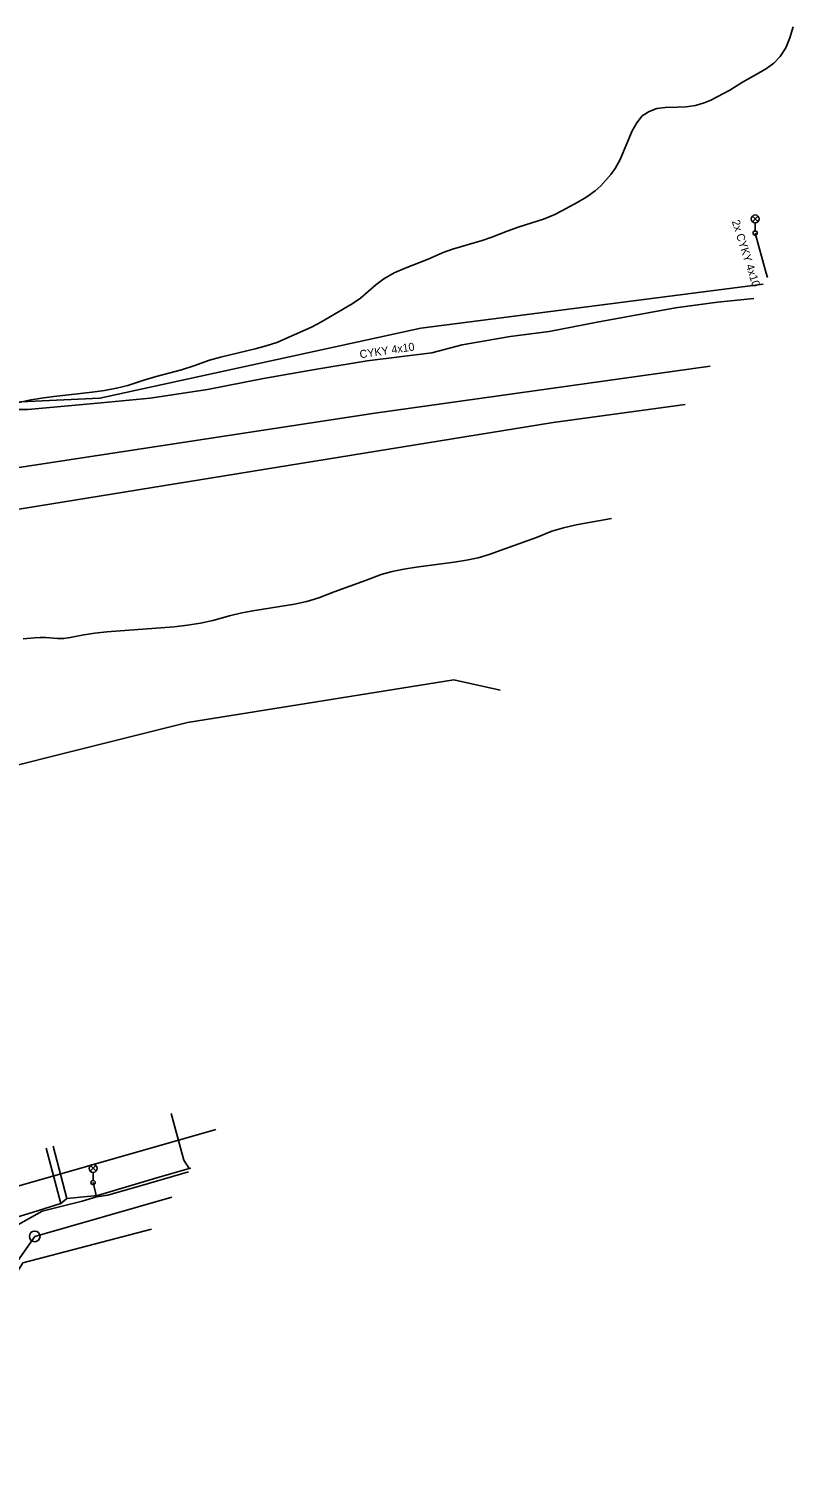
# Model space of a CAD drawing. Extents: x -737422 to -734235, y -1145631 to -1142623.
# Drawn here: x -736808.9 to -736737.2, y -1144825.6 to -1144691 of the extents above; entities that cross this region are included whole.
import ezdxf

# ---------------------------------------------------------------- set-up
doc = ezdxf.new("R2010")
doc.units = 0
for name, color, linetype in [('Vrstva 1', 7, 'Continuous'), ('Vrstva 20', 7, 'Continuous'), ('Vrstva 3', 7, 'Continuous'), ('Vrstva 30', 7, 'Continuous'), ('Vrstva 34', 7, 'Continuous'), ('Vrstva 40', 7, 'Continuous'), ('Vrstva 41', 7, 'Continuous'), ('Vrstva 44', 7, 'Continuous'), ('Vrstva 48', 7, 'Continuous')]:
    doc.layers.add(name, color=color, linetype=linetype)

# ---------------------------------------------------------------- blocks, each defined once
blk = doc.blocks.new('6.200')
at = {"layer": 'Vrstva 1'}
blk.add_circle((0, 0), 1, dxfattribs=at)
blk = doc.blocks.new('6.560')
at = {"layer": 'Vrstva 1'}
for p, q in [((-0.528, 2.124), (0.528, 3.18)), ((0.544, 2.13), (-0.512, 3.188)), ((0, 1.9), (0, 0.4))]:
    blk.add_line(p, q, dxfattribs=at)
for centre, radius in [((0, 2.65), 0.75), ((0, 0), 0.4)]:
    blk.add_circle(centre, radius, dxfattribs=at)

msp = doc.modelspace()

# ---------------------------------------------------------------- linework, layer by layer
at = {"layer": 'Vrstva 1'}
for points in [[(-736737.175, -1144690.787), (-736737.486, -1144691.814), (-736737.879, -1144692.76), (-736738.396, -1144693.582), (-736738.991, -1144694.188), (-736739.681, -1144694.696), (-736740.427, -1144695.142), (-736741.943, -1144695.981), (-736743.129, -1144696.713), (-736743.73, -1144697.046), (-736744.923, -1144697.656), (-736745.521, -1144697.915), (-736746.361, -1144698.156), (-736747.218, -1144698.289), (-736748.049, -1144698.335), (-736749.202, -1144698.341), (-736749.965, -1144698.454), (-736750.696, -1144698.713), (-736751.342, -1144699.146), (-736751.862, -1144699.774), (-736752.286, -1144700.55), (-736753.411, -1144703.224), (-736753.875, -1144704.066), (-736754.292, -1144704.637), (-736754.748, -1144705.172), (-736755.228, -1144705.688), (-736755.747, -1144706.167), (-736756.525, -1144706.723), (-736757.369, -1144707.215), (-736758.879, -1144708.047), (-736759.542, -1144708.387), (-736760.614, -1144708.821)], [(-736760.614, -1144708.821), (-736762.896, -1144709.548), (-736764.015, -1144709.933), (-736765.449, -1144710.504), (-736766.346, -1144710.81), (-736769.126, -1144711.636), (-736770.01, -1144711.953), (-736771.405, -1144712.56), (-736773.565, -1144713.402), (-736774.613, -1144713.854), (-736775.572, -1144714.395), (-736776.323, -1144714.978), (-736777.754, -1144716.215), (-736778.549, -1144716.753), (-736781.483, -1144718.486), (-736782.373, -1144718.93), (-736785.609, -1144720.361), (-736786.604, -1144720.699), (-736787.656, -1144720.98), (-736790.9, -1144721.737), (-736791.928, -1144722.042), (-736793.396, -1144722.574), (-736794.542, -1144722.928), (-736796.916, -1144723.554), (-736798.074, -1144723.896), (-736799.574, -1144724.395), (-736800.639, -1144724.664), (-736801.764, -1144724.872), (-736802.931, -1144725.039), (-736806.518, -1144725.452), (-736807.696, -1144725.607), (-736808.841, -1144725.796), (-736809.936, -1144726.034)], [(-736782.787, -1144744.637), (-736781.679, -1144744.312), (-736780.238, -1144743.747), (-736777.288, -1144742.687), (-736775.838, -1144742.133), (-736774.796, -1144741.839), (-736773.689, -1144741.611), (-736772.537, -1144741.427), (-736768.992, -1144740.961), (-736767.838, -1144740.778), (-736766.729, -1144740.549), (-736765.684, -1144740.255), (-736764.229, -1144739.701), (-736761.267, -1144738.638), (-736759.822, -1144738.069), (-736758.714, -1144737.738), (-736757.54, -1144737.474), (-736754.23, -1144736.872)], [(-736809.405, -1144748.166), (-736808.351, -1144748.044), (-736807.809, -1144748.017), (-736807.263, -1144748.032), (-736806.172, -1144748.118), (-736805.587, -1144748.109), (-736804.979, -1144748.041), (-736803.698, -1144747.782), (-736802.673, -1144747.617), (-736801.545, -1144747.49), (-736795.248, -1144747.012), (-736793.989, -1144746.872), (-736792.771, -1144746.686), (-736791.613, -1144746.438), (-736790.045, -1144745.994), (-736788.879, -1144745.723), (-736787.665, -1144745.5), (-736783.965, -1144744.893), (-736782.787, -1144744.637)], [(-736793.84, -1144797.81), (-736794.33, -1144797.02), (-736795.51, -1144792.65)], [(-736805.86, -1144801.09), (-736807.23, -1144795.89)], [(-736806.59, -1144795.7), (-736805.31, -1144800.62)], [(-736793.84, -1144797.81), (-736796.85, -1144798.66), (-736802.43, -1144800.32)], [(-736793.84, -1144797.81), (-736793.68, -1144797.762)], [(-736802.43, -1144800.32), (-736805.31, -1144800.62)], [(-736814.21, -1144804.51), (-736813.42, -1144803.39), (-736808.97, -1144802.03), (-736805.86, -1144801.09)], [(-736805.31, -1144800.62), (-736805.86, -1144801.09)]]:
    msp.add_lwpolyline(points, dxfattribs=at)
at = {"layer": 'Vrstva 20'}
for points in [[(-736817.09, -1144726.28), (-736802.2, -1144725.6), (-736772.1, -1144719.03), (-736740.001, -1144714.909)], [(-736816.76, -1144825.61), (-736826.1, -1144822.58), (-736824.46, -1144814.68), (-736820.13, -1144804.66), (-736815.63, -1144801.09), (-736791.34, -1144794.15)], [(-736816.76, -1144825.61), (-736811.89, -1144810.62), (-736809.43, -1144806.65), (-736797.378, -1144803.47)]]:
    msp.add_lwpolyline(points, dxfattribs=at)
at = {"layer": 'Vrstva 3'}
for points in [[(-736854.59, -1144736.04), (-736845.04, -1144736.19), (-736836.74, -1144735.66), (-736825.86, -1144734.46), (-736810.21, -1144732.14), (-736776.43, -1144727), (-736744.978, -1144722.591)], [(-736747.316, -1144726.199), (-736759.7, -1144727.86), (-736826.98, -1144738.77)]]:
    msp.add_lwpolyline(points, dxfattribs=at)
at = {"layer": 'Vrstva 30'}
msp.add_lwpolyline([(-736764.657, -1144752.965), (-736769, -1144752), (-736794, -1144756), (-736822, -1144763)], dxfattribs=at)
at = {"layer": 'Vrstva 34'}
for points in [[(-736740.75, -1144710.12), (-736739.72, -1144713.88), (-736739.606, -1144714.299)], [(-736827.16, -1144726.51), (-736826.1, -1144726.47), (-736824.07, -1144727), (-736821.55, -1144727.15), (-736820.19, -1144726.47), (-736818.53, -1144726.33), (-736816.86, -1144726.98), (-736814.87, -1144726.66), (-736808.95, -1144726.66), (-736802.09, -1144726.04), (-736797.5, -1144725.58), (-736792.12, -1144724.79), (-736786.86, -1144723.74), (-736782.04, -1144722.92), (-736777.13, -1144722.08), (-736771.06, -1144721.33), (-736768.23, -1144720.6), (-736763.72, -1144719.8), (-736760.08, -1144719.35), (-736755.57, -1144718.47), (-736748.22, -1144717.12), (-736744.27, -1144716.59), (-736740.872, -1144716.253)], [(-736802.53, -1144800.46), (-736801.45, -1144800.28), (-736797.65, -1144799.19), (-736793.903, -1144798.106)], [(-736802.84, -1144799.11), (-736802.53, -1144800.46)], [(-736821.31, -1144824.32), (-736821.02, -1144822.26), (-736820.47, -1144819.97), (-736819.65, -1144818), (-736819.09, -1144816.33), (-736818.28, -1144815.03), (-736816.17, -1144810.46), (-736814.77, -1144807.22), (-736814.55, -1144806.6), (-736812.83, -1144805.04), (-736810.39, -1144803.37), (-736807.62, -1144801.8), (-736803.87, -1144800.85), (-736802.53, -1144800.46)]]:
    msp.add_lwpolyline(points, dxfattribs=at)
at = {"layer": 'Vrstva 40'}
for points in [[(-736808.32, -1144804.16), (-736795.451, -1144800.496)], [(-736814.26, -1144812.58), (-736808.32, -1144804.16)]]:
    msp.add_lwpolyline(points, dxfattribs=at)

# ---------------------------------------------------------------- block references
at = {"layer": 'Vrstva 41', "xscale": 0.5, "yscale": 0.5}
msp.add_blockref('6.200', (-736808.32, -1144804.16), dxfattribs=at)
at = {"layer": 'Vrstva 44', "xscale": 0.5, "yscale": 0.5}
for p in [(-736740.75, -1144710.12), (-736802.84, -1144799.11)]:
    msp.add_blockref('6.560', p, dxfattribs=at)

# ---------------------------------------------------------------- texts
at = {"layer": 'Vrstva 48'}
for s, rotation, p in [('2x CYKY 4x10', 287.621, (-736742.95, -1144709.02)), ('CYKY 4x10', 8.272, (-736777.79, -1144721.86))]:
    msp.add_text(s, height=0.75, rotation=rotation, dxfattribs=at).set_placement(p)

doc.saveas('drawing.dxf')
